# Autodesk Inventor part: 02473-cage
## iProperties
Author: Administrator
Shininess: 64.0
Angle Display Precision: 2
Document Length Units: 11272
Document Angle Units: 11286
Document Time Units: 11279
Document Mass Units: 11290
Document Length Units Precision: 3
Document Angle Units Precision: 2
Compacted: True
PropertySet Name: _Private Model Information
Created: 2002-04
Part Number: 02473-cage
Material: ASTM A36 HRS
Document SubType Name: Modeling
Designer: Administrator
Control State: 0
Master: False
Checked Out: False
PropertySet Name: Design Tracking Control
Density: 0.0
Volumn: 0.0
Area: 0.0
PropertySet Name: Model Information
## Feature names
1. Revolution1
2. Extrusion1
3. Circular Pattern1
